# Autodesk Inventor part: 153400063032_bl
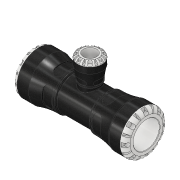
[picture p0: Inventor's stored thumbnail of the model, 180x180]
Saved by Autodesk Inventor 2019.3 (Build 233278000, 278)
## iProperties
Created: 2016-12
Part Number: 153400063032_bl
Material: PVC-Piping
Description: PLASSON G-PLASS  REDUCING TEE 63X32X63
Document SubType Name: Modeling
Designer: KIM
Mass: 664.223 g
Surface Area: 733.008 cm^2
Volume: 474.445 cm^3
Density: 1.4 g/cm^3
Appearance: Black Cast
Author: KIM
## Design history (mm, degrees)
derived "153400.ipt"
feature "Solid1::153400.ipt" dims "ScaleForDerivedMember" = 10
tag "TaggingFeature1"
body "Solid1"
other parameters: "d1" = 39.9 [user parameter], "d2" = 63 [user parameter], "d3" = 78.75 [user parameter], "d4" = 103 [user parameter], "d8" = 87.55 [user parameter], "d13" = 9.7 [user parameter], "d14" = 9.7 [user parameter], "d15" = 0 [user parameter], "d17" = 360 deg [user parameter], "d19" = 8 deg [user parameter], "d20" = 1.26 [user parameter], "d21" = 1.26 [user parameter], "d22" = 8 deg [user parameter], "d24" = 0 [user parameter], "d26" = 360 deg [user parameter], "d33" = 10.3 [user parameter], "d43" = 80.34 [user parameter], "d51" = 1.03 [user parameter], "d54" = 22.05 [user parameter], "d55" = 13.86 [user parameter], "d57" = 19.012 [user parameter], "d58" = 0 [user parameter], "d74" = 0 [user parameter], "d77" = 5.25 [user parameter], "d78" = 95 [user parameter], "d79" = 80.34 [user parameter], "d80" = 271 [user parameter], "d82" = 1.26 [user parameter], "d115" = 360 deg [user parameter], "d139" = 9.7 [user parameter], "d140" = 0 [user parameter], "d142" = 360 deg [user parameter], "d207" = 90 deg [user parameter], "d209" = 23.52 [user parameter], "d210" = 32 [user parameter], "d212" = 58 [user parameter], "d213" = 49.3 [user parameter], "d215" = 45.24 [user parameter], "d216" = 2.66667 [user parameter], "d217" = 56 [user parameter], "d225" = 102 [user parameter], "d226" = 56 [user parameter], "d228" = 18.7425 [user parameter], "d229" = 7.2 [user parameter], "d233" = 7.2 [user parameter], "d234" = 0 [user parameter], "d236" = 360 deg [user parameter], "d238" = 8 deg [user parameter], "d239" = 8 deg [user parameter], "d240" = 1.26 [user parameter], "d241" = 1.26 [user parameter], "d243" = 0 [user parameter], "d245" = 360 deg [user parameter], "d247" = 2.06 [user parameter], "d248" = 5.7 [user parameter], "d249" = 3.36 [user parameter], "d250" = 9.52 [user parameter], "d252" = 11.2 [user parameter], "d253" = 7.36 [user parameter], "d254" = 19.012 [user parameter], "d255" = 0 [user parameter], "d257" = 360 deg [user parameter], "d259" = 1.26 [user parameter], "d261" = 0 [user parameter], "d262" = 2.06 [user parameter], "d264" = 0 [user parameter], "d266" = 0 [user parameter], "d267" = 1.03 [user parameter], "d_" = 63 [user parameter], "E_" = 103 [user parameter], "l_" = 95 [user parameter], "A_" = 102 [user parameter], "H_" = 271 [user parameter], "d_1" = 32 [user parameter], "E_1" = 58 [user parameter], "l_1" = 56 [user parameter], "d9" = 12.125 [user parameter], "d11" = 103 [user parameter], "d12" = 78.75 [user parameter], "d230" = 58 [user parameter], "d232" = 9 [user parameter]
